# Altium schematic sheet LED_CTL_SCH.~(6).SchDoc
size A4
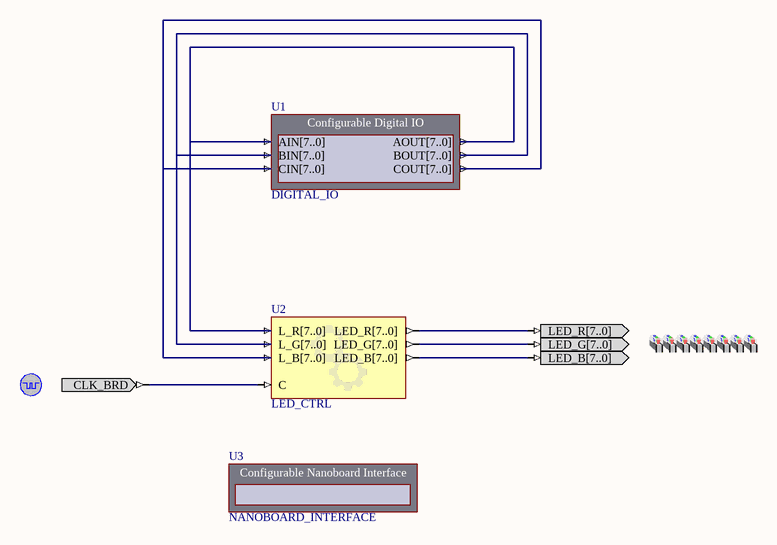
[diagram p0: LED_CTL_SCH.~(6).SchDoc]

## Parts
(Parts that share a designator on the sheet are numbered #1, #2 ... from top to bottom, then left to right.)
?#1  LEDS_RGB  (value not drawn)
?#2  CLOCK_BOARD  (value not drawn)
U1  DIGITAL_IO
U2  LED_CTRL
U3  NANOBOARD_INTERFACE

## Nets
Net?#2_CLK_BRD: ?#2.CLK_BRD U2.C

Not connected (* = marked no-connect by the designer): ?#1 LED_B[7..0] LED_G[7..0] LED_R[7..0]; U1 AIN[7..0] AOUT[7..0] BIN[7..0] BOUT[7..0] CIN[7..0] COUT[7..0]; U2 L_B[7..0] L_G[7..0] L_R[7..0] LED_B[7..0] LED_G[7..0] LED_R[7..0]

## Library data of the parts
?#1 = LEDS_RGB: LEDS RGB; PortComponent: True
?#2 = CLOCK_BOARD: Global System Clock Supply; PortComponent: True
U1 = DIGITAL_IO: Configurable Digital IO; NEXUS_CORE: Instrument; NEXUS_JTAG_DEVICE: True; NEXUS_JTAG_ORDER: 0; ConfigurationParameters: {}Version[2,0]{}StorageType[3]{}InterfaceType[Parallel]{}SchCompWidth[140]{}Input0Name[AIN{1}7..0{2}]{}Input0Width[8]{}Input0InitValue[0]{}Input0Kind[LED Digits]{}Input0SegStyle[Green]{}Input0SegRadix[Binary]{}Input1Name[BIN{1}7..0{2}]{}Input1Width[8]{}Input1InitValue[0]{}Input1Kind[LED Digits]{}Input1SegStyle[Green]{}Input1SegRadix[Binary]{}Input2Name[CIN{1}7..0{2}]{}Input2Width[8]{}Input2InitValue[0]{}Input2Kind[LED Digits]{}Input2SegStyle[Green]{}Input2SegRadix[Binary]{}Output0Name[AOUT{1}7..0{2}]{}Output0Width[8]{}Output0InitValue[0]{}Output0Kind[Slider]{}Output1Name[BOUT{1}7..0{2}]{}Output1Width[8]{}Output1InitValue[0]{}Output1Kind[Slider]{}Output2Name[COUT{1}7..0{2}]{}Output2Width[8]{}Output2InitValue[0]{}Output2Kind[Slider]{}Designator[U1]{}InternalID[0]{}
U2 = LED_CTRL: Configurable LED Controller; ConfigurationParameters: {}Version[1.0]{}NumLEDs[8]{}IntensityControl[Global]{}ConstantIntensity[10]{}BusEnOut[True]{}IsRGB[True]{}
U3 = NANOBOARD_INTERFACE: Configurable Nanoboard Interface; NEXUS_CORE: Instrument; NEXUS_JTAG_DEVICE: True; NEXUS_JTAG_ORDER: 0; ConfiguratorName: DIGITAL_IO_APPLICATION; ConfigurationParameters: {}Version[1.0]{}StorageType[0]{}SubProjectPath[ ]{}ID[{705D4416-0688-4704-92B2-F31CA6A9EEEF}]{}DisabledInDashboard[False]{}AutoRun[False]{}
